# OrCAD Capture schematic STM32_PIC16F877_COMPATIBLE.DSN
size B; title: STM32_PIC16F877_COMPATIBLE; rev: A
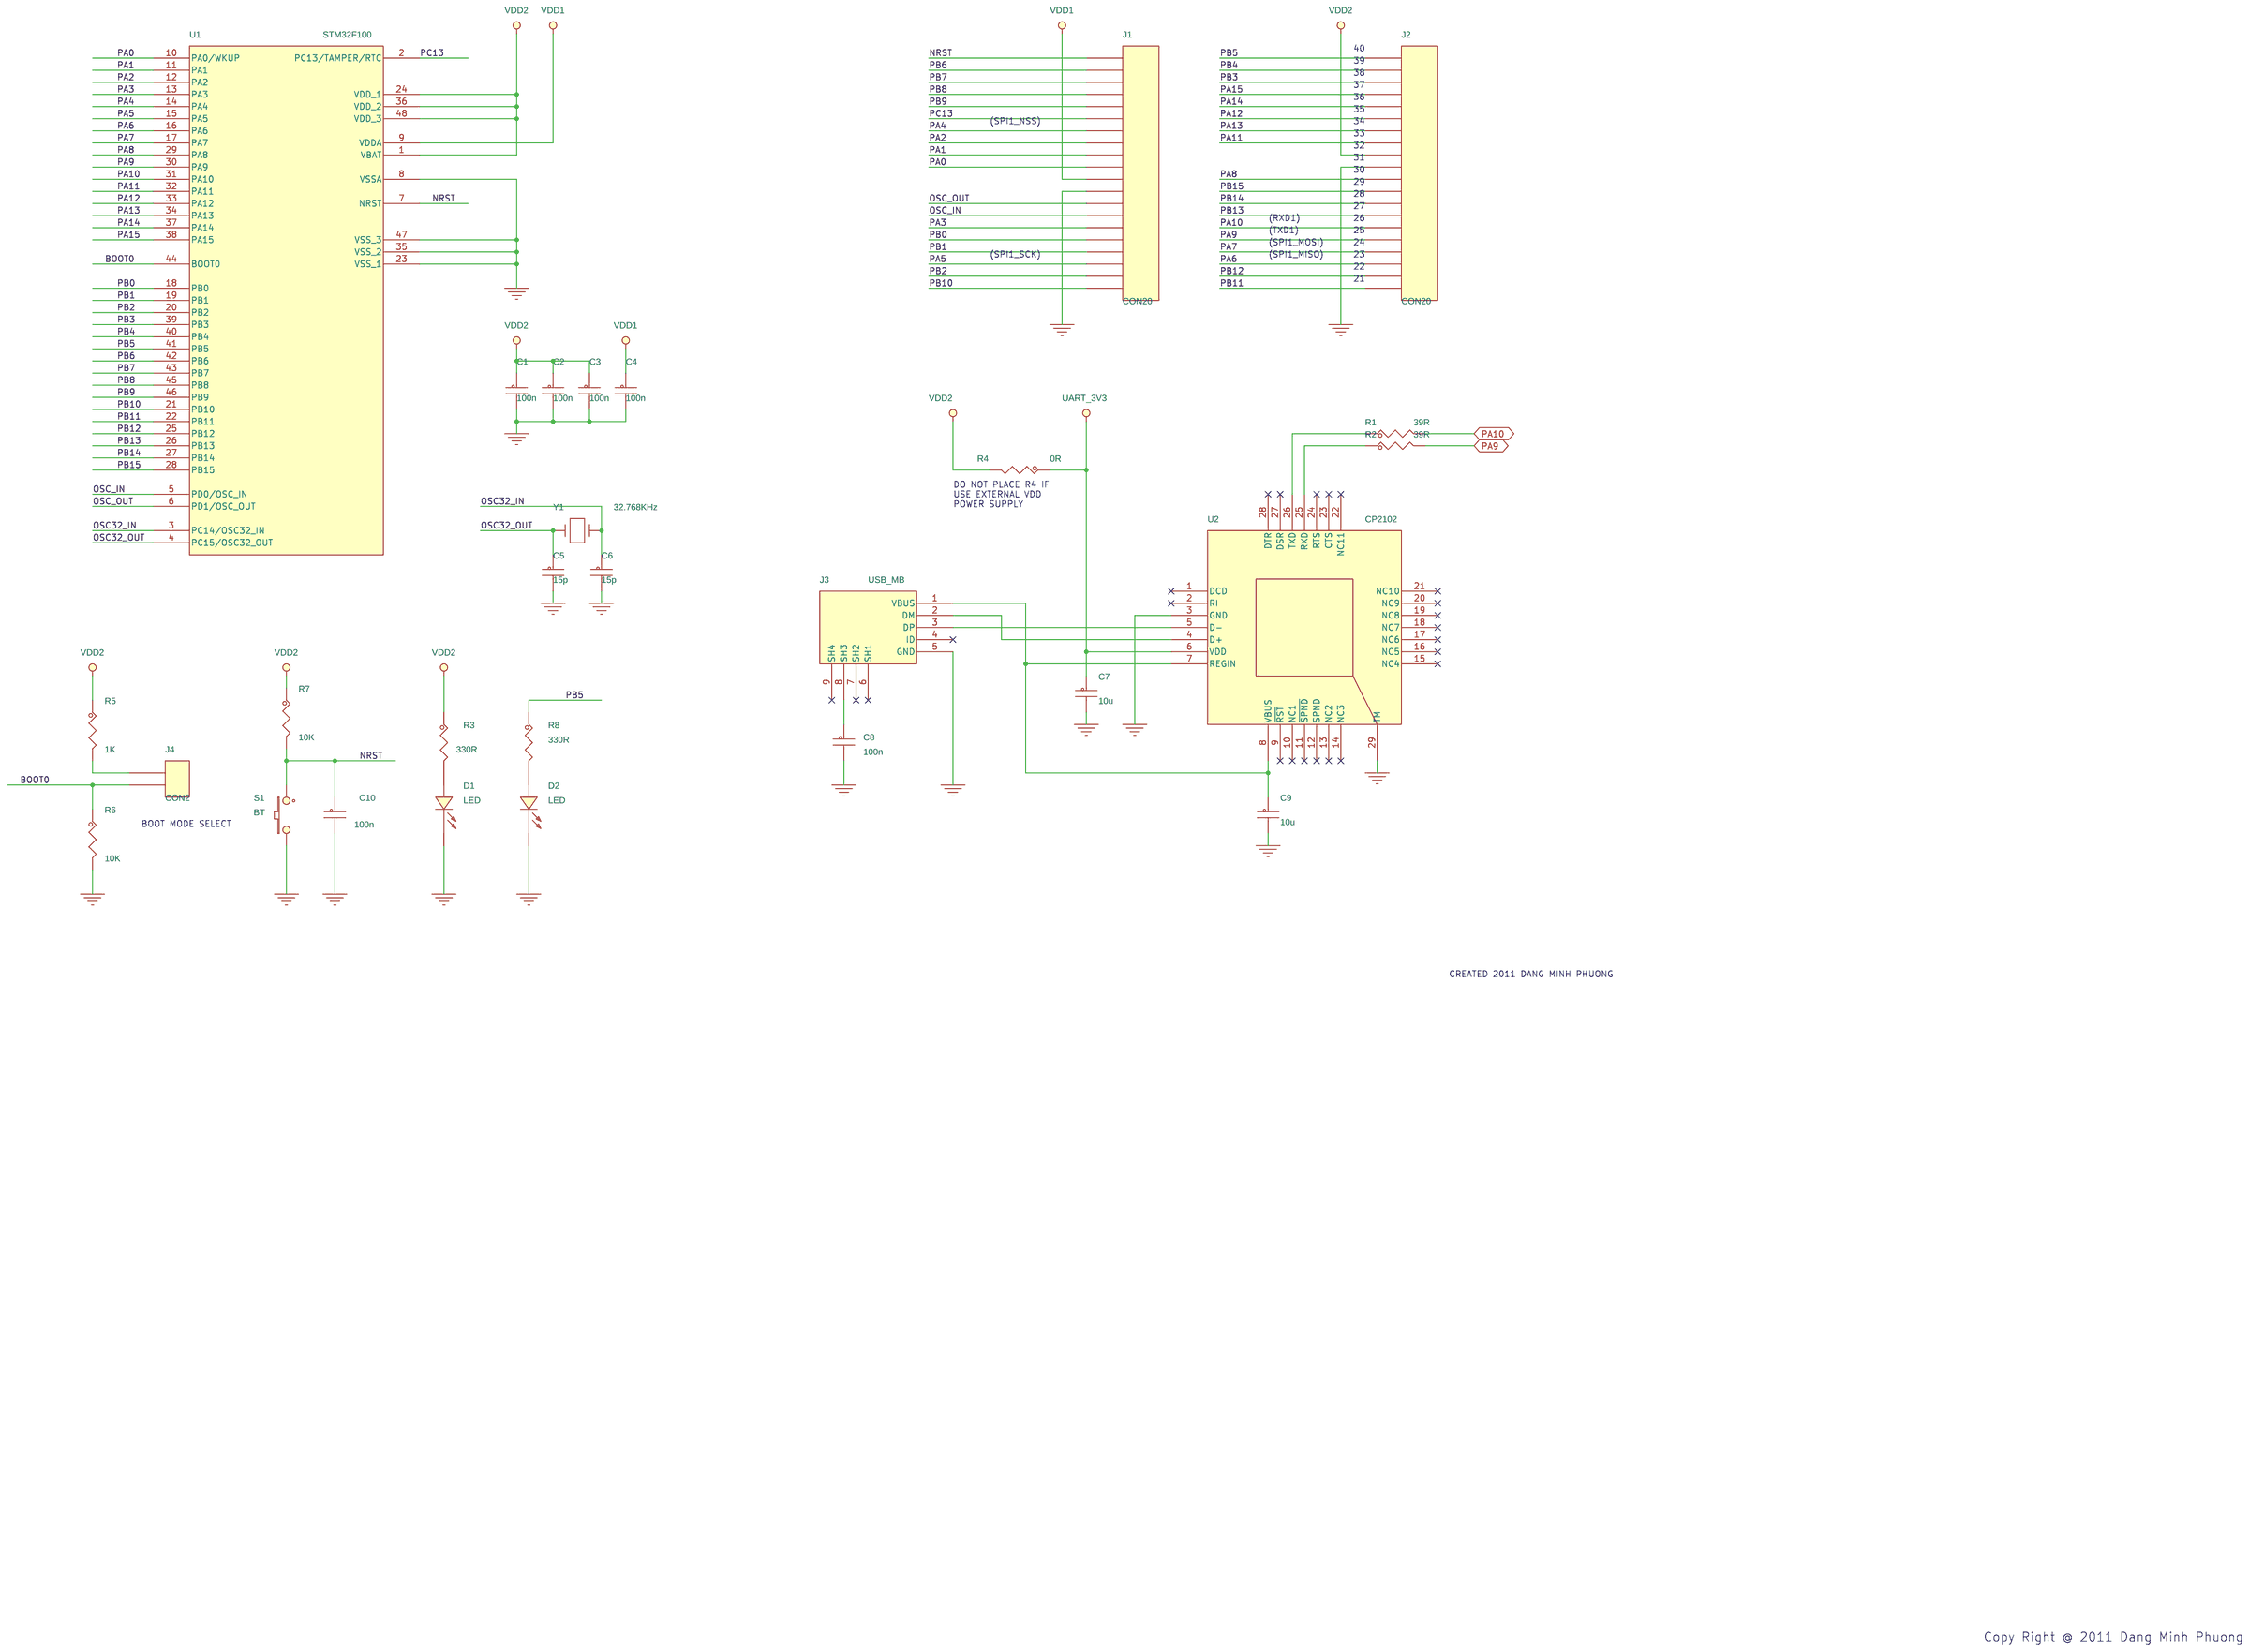
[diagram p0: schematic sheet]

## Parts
C1  100n  [CAP0603_B]
C2  100n  [CAP0603_B]
C3  100n  [CAP0603_B]
C4  100n  [CAP0603_B]
C5  15p  [CAP0603_B]
C6  15p  [CAP0603_B]
C7  10u  [CAP0603_B1]
C8  100n  [CAP0603_B1]
C9  10u  [CAP0603_B1]
C10  100n  [CAP0603_B1]
D1  LED  [LEDC2012X120M]
D2  LED  [LEDC2012X120M]
J1  CON20  [HDR254M-1X20]
J2  CON20  [HDR254M-1X20]
J3  USB_MB  [HIROSE-US60-MB-5ST]
J4  CON2  [HDR254M-1X2]
R1  39R  [RES0603_B1]
R2  39R  [RES0603_B1]
R3  330R  [RES0603_B1]
R4  0R  [RES0603_B1]
R5  1K  [RES0603_B1]
R6  10K  [RES0603_B1]
R7  10K  [RES0603_B1]
R8  330R  [RES0603_B1]
S1  BT  [BUTTON_RST_CIRCLE]
U1  STM32F100  [LQFP48L]
U2  CP2102  [CP2102]
Y1  32.768KHz  [ABS10]

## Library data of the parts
C1-C10 = C1005_0
D1 D2 = LED_0
J1 J2 = CON20
J3 = CON9_2
J4 = CON2
R1-R8 = R_0
S1 = SW_PUSHBUTTON_1
U1 = STM32F100_1
U2 = CP2102_2
Y1 = ZTA

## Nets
GND: C1.2 C2.2 C3.2 C4.2 C5.2 C6.2 C7.2 C8.2 C9.2 C10.2 D1.C D2.C J1.12 J2.10 J3.5(GND) R6.2 S1.2 U1.8(VSSA) U1.23(VSS_1) U1.35(VSS_2) U1.47(VSS_3) U2.3(GND) U2.29(TM)
VDD1: C4.1 J1.11 U1.9(VDDA)
VDD2: C1.1 C2.1 C3.1 J2.9 R3.1 R4.2 R5.1 R7.1 U1.1(VBAT) U1.24(VDD_1) U1.36(VDD_2) U1.48(VDD_3)
BOOT0: J4.2 R6.1 U1.44(BOOT0)
NRST: C10.1 J1.1 R7.2 S1.1 U1.7(NRST)
OSC32_IN: C6.1 U1.3(PC14/OSC32_IN) Y1.1
OSC32_OUT: C5.1 U1.4(PC15/OSC32_OUT) Y1.2
OSC_IN: J1.14 U1.5(PD0/OSC_IN)
OSC_OUT: J1.13 U1.6(PD1/OSC_OUT)
PA0: J1.10 U1.10(PA0/WKUP)
PA1: J1.9 U1.11(PA1)
PA2: J1.8 U1.12(PA2)
PA3: J1.15 U1.13(PA3)
PA4: J1.7 U1.14(PA4)
PA5: J1.18 U1.15(PA5)
PA6: J2.18 U1.16(PA6)
PA7: J2.17 U1.17(PA7)
PA8: J2.11 U1.29(PA8)
PA9: J2.16 R2.2 U1.30(PA9)
PA10: J2.15 R1.2 U1.31(PA10)
PA11: J2.8 U1.32(PA11)
PA12: J2.6 U1.33(PA12)
PA13: J2.7 U1.34(PA13)
PA14: J2.5 U1.37(PA14)
PA15: J2.4 U1.38(PA15)
PB0: J1.16 U1.18(PB0)
PB1: J1.17 U1.19(PB1)
PB2: J1.19 U1.20(PB2)
PB3: J2.3 U1.39(PB3)
PB4: J2.2 U1.40(PB4)
PB5: J2.1 R8.1 U1.41(PB5)
PB6: J1.2 U1.42(PB6)
PB7: J1.3 U1.43(PB7)
PB8: J1.4 U1.45(PB8)
PB9: J1.5 U1.46(PB9)
PB10: J1.20 U1.21(PB10)
PB11: J2.20 U1.22(PB11)
PB12: J2.19 U1.25(PB12)
PB13: J2.14 U1.26(PB13)
PB14: J2.13 U1.27(PB14)
PB15: J2.12 U1.28(PB15)
PC13: J1.6 U1.2(PC13/TAMPER/RTC)
UART_3V3: C7.1 R4.1 U2.6(VDD)
N15023592: C9.1 J3.1(VBUS) U2.7(REGIN) U2.8(VBUS)
N15023608: J3.3(DP) U2.5(D-)
N15023612: J3.2(DM) U2.4(D+)
N15023760: R1.1 U2.26(TXD)
N15023764: R2.1 U2.25(RXD)
N15029027: C8.1 J3.8(SH3)
N15029202: J4.1 R5.2
N15031219: D1.A R3.2
N15031256: D2.A R8.2

Not connected (* = marked no-connect by the designer): J3 4(ID)* 6(SH1)* 7(SH2)* 9(SH4)*; U2 1(DCD)* 2(RI)* 9(~{RST})* 10(NC1)* 11(~{SPND})* 12(SPND)* 13(NC2)* 14(NC3)* 15(NC4)* 16(NC5)* 17(NC6)* 18(NC7)* 19(NC8)* 20(NC9)* 21(NC10)* 22(NC11)* 23(CTS)* 24(RTS)* 27(DSR)* 28(DTR)*

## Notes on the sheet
- 40
- 39
- 38
- 37
- 36
- 35
- (SPI1_NSS)
- 33
- 34
- 32
- 31
- 30
- 29
- 27
- 28
- (RXD1)
- 26
- (TXD1)
- 25
- (SPI1_MOSI)
- 24
- (SPI1_SCK)
- (SPI1_MISO)
- 23
- 22
- 21
- DO NOT PLACE R4 IF
  USE EXTERNAL VDD
  POWER SUPPLY
- BOOT MODE SELECT
- CREATED 2011 DANG MINH PHUONG
- Copy Right @ 2011 Dang Minh Phuong
